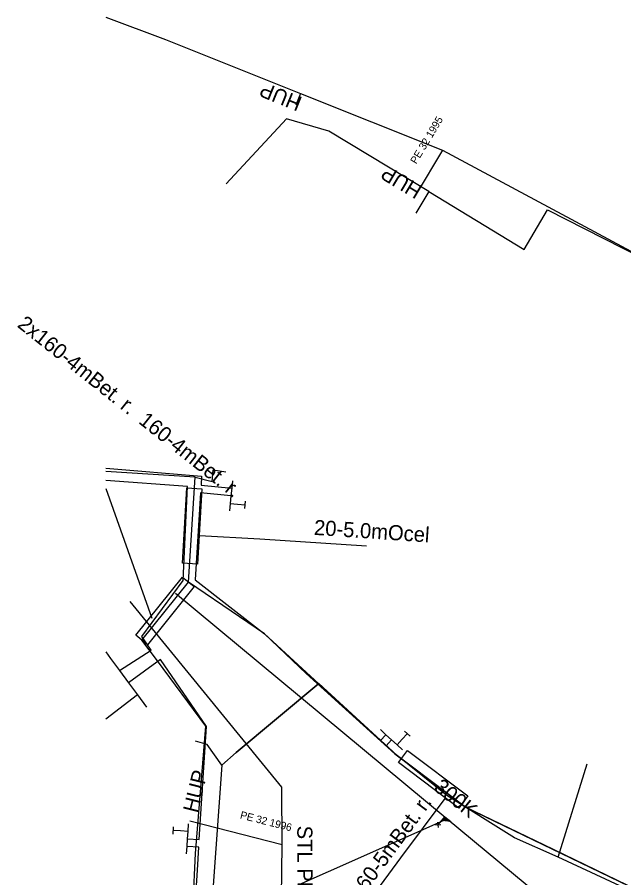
# Model space of a CAD drawing. Extents: x -746464 to -745690, y -1051581 to -1049993.
# Drawn here: x -746464 to -746423.8, y -1051012.9 to -1050955.9 of the extents above; entities that cross this region are included whole.
import ezdxf

# ---------------------------------------------------------------- set-up
doc = ezdxf.new("R2010")
doc.units = 0
for name, color, linetype in [('04_CETIN_sdelovaci_podzem', 7, 'Continuous'), ('48_Prazs_plynarenska_STL', 7, 'Continuous'), ('48_Prazs_plynarenska_STL_popisy', 7, 'Continuous'), ('51_PVaK_kanal_jednotna_neoverena poloha_pripojka', 7, 'Continuous'), ('51_PVaK_kanal_jednotna_overena poloha_rad', 7, 'Continuous'), ('51_PVaK_kanal_objekty', 7, 'Continuous'), ('51_PVaK_kanal_popisy', 7, 'Continuous'), ('55_PREdi_chranicky', 7, 'Continuous'), ('55_PREdi_NN', 7, 'Continuous'), ('55_PREdi_NN_pripojovaci_misto', 7, 'Continuous'), ('55_PREdi_stavby_popisy', 7, 'Continuous')]:
    doc.layers.add(name, color=color, linetype=linetype)

msp = doc.modelspace()

# ---------------------------------------------------------------- linework, layer by layer
at = {"layer": '04_CETIN_sdelovaci_podzem'}
for points in [[(-746436.71, -1050967.48), (-746443.33, -1050963.47), (-746446.13, -1050962.67), (-746450.14, -1050966.96)], [(-746436.71, -1050967.48), (-746437.58, -1050968.91)], [(-746436.71, -1050967.48), (-746430.4, -1050971.31), (-746428.85, -1050968.68), (-746418.92, -1050973.73)], [(-746430.4, -1050971.31), (-746428.85, -1050968.68)], [(-746428.14, -1051011.55), (-746431.04, -1051010.27), (-746435.52, -1051007.47), (-746438.82, -1051004.82), (-746443.99, -1051000.06), (-746449.47, -1051004.62), (-746450.41, -1051005.45)], [(-746449.47, -1051004.62), (-746443.99, -1051000.06)], [(-746450.41, -1051005.45), (-746451.38, -1051004.08), (-746452.16, -1051003.86)], [(-746450.41, -1051005.45), (-746451.4, -1051018.95)], [(-746428.14, -1051011.55), (-746426.22, -1051005.36)], [(-746410.72, -1051017.45), (-746422.5, -1051014.18), (-746428.14, -1051011.55)]]:
    msp.add_lwpolyline(points, dxfattribs=at)
at = {"layer": '48_Prazs_plynarenska_STL'}
for points in [[(-746458.107, -1050955.931), (-746454.15, -1050957.41), (-746445.22, -1050960.98), (-746435.81, -1050964.74), (-746422.44, -1050971.9), (-746414.71, -1050975.94), (-746404.06, -1050981.43), (-746399.66, -1050984.21), (-746380.77, -1050996.22), (-746365.51, -1051001.19), (-746365.059, -1051001.349)], [(-746445.22, -1050960.98), (-746445.528, -1050961.758)], [(-746435.81, -1050964.74), (-746437.558, -1050967.655)], [(-746446.05, -1051027.64), (-746445.88, -1051025.06), (-746446.59, -1051024.71), (-746446.525, -1051019.382), (-746446.42, -1051010.73), (-746446.44, -1051006.92), (-746456.499, -1050994.627)], [(-746446.42, -1051010.73), (-746452.537, -1051009.168)]]:
    msp.add_lwpolyline(points, dxfattribs=at)
at = {"layer": '51_PVaK_kanal_jednotna_neoverena poloha_pripojka'}
msp.add_line((-746453.83, -1051017.13), (-746435.493, -1051009.003), dxfattribs=at)
at = {"layer": '51_PVaK_kanal_jednotna_overena poloha_rad'}
msp.add_lwpolyline([(-746453.49, -1050994.06), (-746435.493, -1051009.003), (-746424.26, -1051018.33)], dxfattribs=at)
at = {"layer": '51_PVaK_kanal_objekty'}
for p, q in [((-746435.917, -1051009.398), (-746436.263, -1051009.431)), ((-746436.083, -1051009.587), (-746436.116, -1051009.238))]:
    msp.add_line(p, q, dxfattribs=at)
for points in [[(-746436.098, -1051009.416), (-746435.649, -1051008.876), (-746435.263, -1051009.196), (-746435.852, -1051009.119)], [(-746435.778, -1051009.089), (-746435.648, -1051008.931), (-746435.401, -1051009.136), (-746435.781, -1051009.087)], [(-746435.703, -1051009.056), (-746435.637, -1051008.977), (-746435.511, -1051009.082), (-746435.705, -1051009.053)]]:
    msp.add_lwpolyline(points, dxfattribs=at)
at = {"layer": '55_PREdi_chranicky'}
for points in [[(-746452.732, -1050987.095), (-746451.734, -1050987.155), (-746452.033, -1050992.147), (-746453.031, -1050992.087), (-746452.732, -1050987.095)], [(-746453.035, -1050993.004), (-746452.255, -1050993.63), (-746455.339, -1050997.479), (-746456.119, -1050996.853), (-746453.035, -1050993.004)], [(-746434.135, -1051007.497), (-746434.735, -1051008.297), (-746438.726, -1051005.285), (-746438.126, -1051004.485), (-746434.135, -1051007.497)]]:
    msp.add_lwpolyline(points, close=True, dxfattribs=at)
at = {"layer": '55_PREdi_NN'}
for p, q in [((-746452.18, -1050986.384), (-746458.107, -1050986.002)), ((-746456, -1051000.81), (-746458.107, -1051002.402))]:
    msp.add_line(p, q, dxfattribs=at)
for points in [[(-746458.107, -1050985.788), (-746451.755, -1050986.31), (-746451.782, -1050986.918), (-746449.767, -1050987.126)], [(-746452.18, -1050986.384), (-746451.064, -1050986.675), (-746450.993, -1050985.899), (-746450.147, -1050986.04)], [(-746428.573, -1051010.988), (-746422.853, -1051013.746), (-746410.997, -1051017.845), (-746410.472, -1051016.082), (-746409.087, -1051009.798), (-746407.756, -1050996.625), (-746408.308, -1050986.107), (-746409.348, -1050986.162)], [(-746457.187, -1050999.197), (-746455.098, -1050997.832), (-746455.71, -1050996.938), (-746452.979, -1050993.219), (-746452.697, -1050987.004), (-746458.107, -1050986.613)], [(-746452.617, -1050993.34), (-746452.18, -1050986.384)], [(-746449.716, -1050986.629), (-746449.767, -1050987.126), (-746449.819, -1050987.624), (-746449.87, -1050988.121), (-746449.921, -1050988.618)], [(-746449.819, -1050987.624), (-746451.834, -1050987.416), (-746452.179, -1050993.183), (-746447.6, -1050996.762), (-746442.61, -1051001.351)], [(-746449.87, -1050988.121), (-746449.373, -1050988.172)], [(-746454.683, -1050998.557), (-746455.707, -1050997.184), (-746452.617, -1050993.34)], [(-746449.257, -1050995.632), (-746452.617, -1050993.34)], [(-746410.997, -1051017.845), (-746419.383, -1051015.06), (-746422.853, -1051013.746), (-746428.45, -1051011.047), (-746434.279, -1051008.237), (-746438.969, -1051004.698), (-746442.457, -1051001.544), (-746444.842, -1050999.388), (-746447.6, -1050996.762), (-746449.257, -1050995.632)], [(-746458.107, -1050997.948), (-746457.781, -1050998.391), (-746457.187, -1050999.197), (-746456.594, -1051000.003), (-746456, -1051000.81), (-746455.409, -1051001.613)], [(-746458.107, -1051031.321), (-746454.716, -1051030.526), (-746453.093, -1051028.691), (-746452.617, -1051021.23), (-746452.169, -1051011.309), (-746451.471, -1051002.864), (-746454.683, -1050998.557)], [(-746452.687, -1051010.337), (-746451.91, -1051010.387), (-746451.426, -1051002.893), (-746454.487, -1050998.468), (-746456.594, -1051000.003)], [(-746442.61, -1051001.351), (-746439.913, -1051003.83), (-746439.555, -1051003.439)], [(-746439.924, -1051003.102), (-746439.555, -1051003.439), (-746439.187, -1051003.777), (-746438.818, -1051004.115), (-746438.449, -1051004.452)], [(-746439.187, -1051003.777), (-746439.545, -1051004.168), (-746438.969, -1051004.698), (-746434.279, -1051008.237), (-746428.573, -1051010.988)], [(-746438.818, -1051004.115), (-746438.48, -1051003.746)], [(-746452.751, -1051011.335), (-746452.719, -1051010.837), (-746452.687, -1051010.337), (-746452.655, -1051009.839), (-746452.623, -1051009.34)], [(-746452.655, -1051009.839), (-746453.154, -1051009.806)], [(-746452.04, -1051012.399), (-746451.942, -1051010.887), (-746452.719, -1051010.837)], [(-746458.107, -1051031.32), (-746454.716, -1051030.526), (-746453.093, -1051028.691), (-746452.04, -1051012.399)]]:
    msp.add_lwpolyline(points, dxfattribs=at)
at = {"layer": '55_PREdi_NN_pripojovaci_misto'}
for p, q in [((-746448.897, -1050988.465), (-746448.853, -1050987.967)), ((-746449.373, -1050988.172), (-746448.875, -1050988.216)), ((-746438.48, -1051003.746), (-746438.145, -1051003.374)), ((-746437.96, -1051003.542), (-746438.331, -1051003.207)), ((-746453.64, -1051009.53), (-746453.666, -1051010.029)), ((-746453.154, -1051009.806), (-746453.653, -1051009.78))]:
    msp.add_line(p, q, dxfattribs=at)
at = {"layer": '55_PREdi_stavby_popisy'}
msp.add_line((-746458.107, -1050987.148), (-746455.06, -1050995.733), dxfattribs=at)
for points in [[(-746451.904, -1050990.242), (-746447.902, -1050990.471), (-746440.849, -1050990.937)], [(-746443.167, -1051017.847), (-746438.568, -1051011.602), (-746435.621, -1051007.658)]]:
    msp.add_lwpolyline(points, dxfattribs=at)

# ---------------------------------------------------------------- texts
at = {"layer": '48_Prazs_plynarenska_STL_popisy'}
for s, height, rotation, p in [('HUP', 1, 158, (-746445.028, -1050961.258)), ('PE 32 1995', 0.5, 59.0507, (-746437.546, -1050965.691)), ('HUP', 1, 149, (-746437.058, -1050967.155)), ('HUP', 1, 76, (-746452.037, -1051008.668)), ('PE 32 1996', 0.5, 345.6754, (-746449.246, -1051008.976)), ('STL PE 63 1996', 1, 270.3008, (-746445.427, -1051009.464))]:
    msp.add_text(s, height=height, rotation=rotation, dxfattribs=at).set_placement(p)
at = {"layer": '51_PVaK_kanal_popisy'}
msp.add_text('300K', height=1, rotation=321.2978, dxfattribs=at).set_placement((-746436.452, -1051007.054))
at = {"layer": '55_PREdi_stavby_popisy'}
for s, rotation, p in [('2x160-4mBet. r.  160-4mBet. r.', 321.5513, (-746464.021, -1050976.395)), ('20-5.0mOcel', 356.2265, (-746444.342, -1050990.205)), ('160-5mBet. r.', 53.6318, (-746441.27, -1051014.428))]:
    msp.add_text(s, height=1, rotation=rotation, dxfattribs=at).set_placement(p)

doc.saveas('drawing.dxf')
